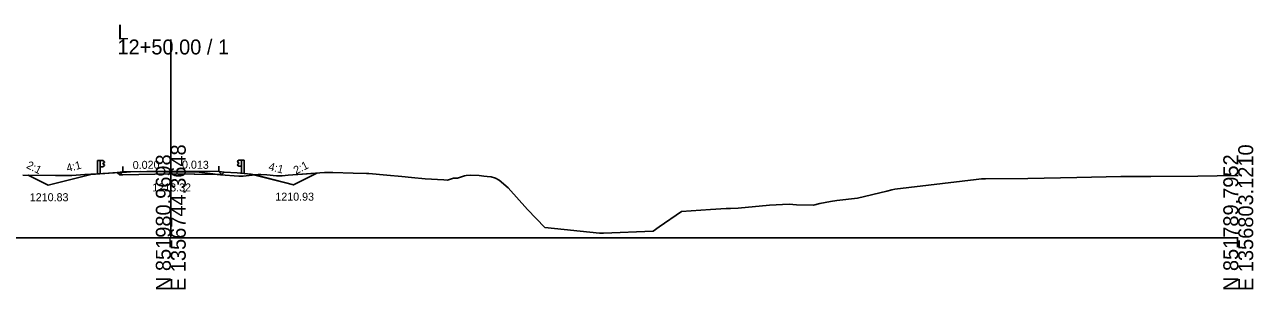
# Model space of a CAD drawing. Extents: x -26 to 3203, y -10 to 4066.
# Drawn here: x 172.6 to 402.8, y 1990.3 to 2039.9 of the extents above; entities that cross this region are included whole.
import ezdxf

# ---------------------------------------------------------------- set-up
doc = ezdxf.new("R2010")
doc.units = 0
for name, color, linetype in [('Exist Cross Section Cell', 7, 'Continuous'), ('Exist XS Center Line Elevation Label', 7, 'Continuous'), ('Exist XS Ground Line', 7, 'Continuous'), ('Prop XS Ditch Slope Text', 7, 'Continuous'), ('Prop XS Ditch Standard Text', 7, 'Continuous'), ('Prop XS Dump Level', 7, 'Continuous'), ('Prop XS Earthwork Shape', 7, 'Continuous'), ('Prop XS EOT Tick Mark', 7, 'Continuous'), ('Prop XS Finish Grade', 7, 'Continuous'), ('Prop XS Finish Grade Earthwork', 7, 'Continuous'), ('Prop XS Finish Grade Pavement', 7, 'Continuous'), ('Prop XS Guardrail', 7, 'Continuous'), ('Prop XS Pvmt Edge Slope', 7, 'Continuous'), ('Prop XS SE Text', 7, 'Continuous'), ('Prop XS Side Slope Text', 7, 'Continuous'), ('Prop XS Subgrade Earthwork', 7, 'Continuous')]:
    doc.layers.add(name, color=color, linetype=linetype)

msp = doc.modelspace()

# ---------------------------------------------------------------- linework, layer by layer
at = {"layer": 'Exist Cross Section Cell'}
for p, q in [((200, 2000), (200, 2037.13)), ((0, 2000), (200, 2000)), ((200, 2000), (400, 2000))]:
    msp.add_line(p, q, dxfattribs=at)
at = {"layer": 'Exist XS Ground Line'}
for p, q in [((183.89, 2011.81), (191.69, 2012.3)), ((191.69, 2012.3), (192.44, 2012.34)), ((192.44, 2012.34), (194.32, 2012.38)), ((194.32, 2012.38), (198.68, 2012.33)), ((198.68, 2012.33), (200, 2012.32)), ((200, 2012.32), (205.31, 2012.27)), ((205.31, 2012.27), (206.9, 2012.08)), ((172.29, 2011.71), (178.41, 2011.64)), ((178.41, 2011.64), (181.45, 2011.63)), ((181.45, 2011.63), (183.89, 2011.81)), ((206.9, 2012.08), (209.33, 2011.75)), ((209.33, 2011.75), (212.72, 2011.54)), ((212.72, 2011.54), (213.53, 2011.51)), ((213.53, 2011.51), (216.37, 2011.82)), ((216.37, 2011.82), (216.87, 2011.86)), ((216.87, 2011.86), (217.97, 2011.75)), ((217.97, 2011.75), (219.82, 2011.56)), ((219.82, 2011.56), (220.52, 2011.59)), ((220.52, 2011.59), (220.86, 2011.61)), ((220.86, 2011.61), (222, 2011.71)), ((222, 2011.71), (228.8, 2012.22)), ((228.8, 2012.22), (229.11, 2012.21)), ((229.11, 2012.21), (229.42, 2012.22)), ((229.42, 2012.22), (229.77, 2012.22)), ((229.77, 2012.22), (230.38, 2012.23)), ((230.38, 2012.23), (234.17, 2012.09)), ((234.17, 2012.09), (236.66, 2012.01)), ((236.66, 2012.01), (237.09, 2012.01)), ((237.09, 2012.01), (240.47, 2011.73)), ((240.47, 2011.73), (243.27, 2011.49)), ((243.27, 2011.49), (245.1, 2011.3)), ((245.1, 2011.3), (247.68, 2011.04)), ((247.68, 2011.04), (251.16, 2010.85)), ((251.16, 2010.85), (251.82, 2010.79)), ((251.82, 2010.79), (252.95, 2011.14)), ((252.95, 2011.14), (253.69, 2011.18)), ((253.69, 2011.18), (255, 2011.6)), ((255, 2011.6), (255.35, 2011.62)), ((255.35, 2011.62), (256.22, 2011.69)), ((256.22, 2011.69), (257.76, 2011.65)), ((257.76, 2011.65), (258.64, 2011.53)), ((258.64, 2011.53), (259.3, 2011.45)), ((259.3, 2011.45), (260.04, 2011.4)), ((260.04, 2011.4), (260.81, 2011.17)), ((260.81, 2011.17), (261.54, 2010.79)), ((261.54, 2010.79), (263.23, 2009.37)), ((335.67, 2009.1), (350.88, 2010.9)), ((350.88, 2010.9), (351.89, 2011)), ((351.89, 2011), (352.63, 2011)), ((352.63, 2011), (360.6, 2011.09)), ((360.6, 2011.09), (369.76, 2011.29)), ((369.76, 2011.29), (378.02, 2011.45)), ((378.02, 2011.45), (383.64, 2011.46)), ((383.64, 2011.46), (392.42, 2011.55)), ((392.42, 2011.55), (396.05, 2011.59)), ((396.05, 2011.59), (400, 2011.62)), ((263.23, 2009.37), (266.83, 2005.27)), ((328.67, 2007.38), (334.13, 2008.73)), ((334.13, 2008.73), (335.1, 2008.96)), ((335.1, 2008.96), (335.67, 2009.1)), ((301.11, 2005.25), (304.05, 2005.44)), ((304.05, 2005.44), (304.84, 2005.49)), ((304.84, 2005.49), (306.3, 2005.55)), ((306.3, 2005.55), (312.17, 2006.07)), ((312.17, 2006.07), (315.88, 2006.28)), ((315.88, 2006.28), (317.26, 2006.18)), ((317.26, 2006.18), (320.39, 2006.1)), ((320.39, 2006.1), (321.58, 2006.38)), ((321.58, 2006.38), (323.61, 2006.77)), ((323.61, 2006.77), (324.81, 2006.97)), ((324.81, 2006.97), (328.67, 2007.38)), ((266.83, 2005.27), (270.08, 2001.88)), ((291.47, 2002.02), (295.66, 2004.92)), ((295.66, 2004.92), (301.11, 2005.25)), ((270.08, 2001.88), (280.34, 2000.87)), ((280.34, 2000.87), (280.72, 2000.82)), ((280.72, 2000.82), (281.1, 2000.84)), ((281.1, 2000.84), (290.35, 2001.19)), ((290.35, 2001.19), (291.47, 2002.02))]:
    msp.add_line(p, q, dxfattribs=at)
at = {"layer": 'Prop XS Dump Level'}
for p, q in [((191, 2012.31), (200, 2012.49)), ((200, 2012.49), (209, 2012.37))]:
    msp.add_line(p, q, dxfattribs=at)
at = {"layer": 'Prop XS Earthwork Shape'}
for points in [[(190.45, 2011.76), (190.01, 2012.19), (191.69, 2012.3), (192.44, 2012.34), (194.32, 2012.38), (198.68, 2012.33), (200, 2012.32), (205.31, 2012.27), (206.9, 2012.08), (208.69, 2011.83), (200, 2011.95), (191, 2011.77)], [(209.55, 2011.82), (210.02, 2012.3), (212.42, 2012.12), (215, 2011.93), (215.74, 2011.75), (213.53, 2011.51), (212.72, 2011.54), (209.33, 2011.75), (208.69, 2011.83), (209, 2011.83)], [(187.62, 2012.04), (187.58, 2012.04), (185, 2011.83), (177, 2009.83), (173.27, 2011.7), (178.41, 2011.64), (181.45, 2011.63), (183.89, 2011.81)], [(190.01, 2012.19), (189.98, 2012.23), (187.62, 2012.04)], [(223, 2009.93), (227.35, 2012.11), (222, 2011.71), (220.86, 2011.61), (220.52, 2011.59), (219.82, 2011.56), (217.97, 2011.75), (216.87, 2011.86), (216.37, 2011.82), (215.74, 2011.75)]]:
    msp.add_lwpolyline(points, close=True, dxfattribs=at)
at = {"layer": 'Prop XS EOT Tick Mark'}
for p, q in [((191, 2012.31), (191, 2013.31)), ((209, 2012.37), (209, 2013.37))]:
    msp.add_line(p, q, dxfattribs=at)
at = {"layer": 'Prop XS Finish Grade'}
for p, q in [((191, 2012.31), (189.98, 2012.23)), ((209, 2012.37), (210.02, 2012.3))]:
    msp.add_line(p, q, dxfattribs=at)
at = {"layer": 'Prop XS Finish Grade Earthwork'}
for p, q in [((210.02, 2012.3), (212.42, 2012.12)), ((177, 2009.83), (173.27, 2011.7)), ((185, 2011.83), (177, 2009.83)), ((187.58, 2012.04), (185, 2011.83)), ((189.98, 2012.23), (187.58, 2012.04)), ((212.42, 2012.12), (215, 2011.93)), ((215, 2011.93), (223, 2009.93)), ((223, 2009.93), (227.35, 2012.11))]:
    msp.add_line(p, q, dxfattribs=at)
at = {"layer": 'Prop XS Finish Grade Pavement'}
for p, q in [((191, 2012.31), (200, 2012.49)), ((200, 2012.49), (209, 2012.37))]:
    msp.add_line(p, q, dxfattribs=at)
at = {"layer": 'Prop XS Guardrail'}
for p, q in [((186.26, 2014.43), (186.76, 2014.43)), ((186.26, 2011.93), (186.26, 2014.43)), ((186.76, 2014.43), (187.26, 2014.43)), ((186.76, 2014.43), (186.76, 2011.93)), ((187.26, 2013.3), (186.76, 2013.3)), ((187.26, 2014.43), (187.55, 2014.23)), ((187.55, 2014.11), (187.26, 2013.91)), ((187.26, 2013.91), (187.26, 2013.82)), ((187.26, 2013.82), (187.55, 2013.62)), ((187.55, 2013.5), (187.26, 2013.3)), ((187.55, 2014.23), (187.58, 2014.17)), ((187.58, 2014.17), (187.55, 2014.11)), ((187.55, 2013.62), (187.58, 2013.56)), ((187.58, 2013.56), (187.55, 2013.5)), ((212.47, 2014.32), (212.44, 2014.26)), ((212.44, 2014.26), (212.47, 2014.2)), ((212.47, 2013.71), (212.44, 2013.65)), ((212.44, 2013.65), (212.47, 2013.59)), ((212.76, 2014.52), (212.47, 2014.32)), ((212.47, 2014.2), (212.76, 2014)), ((212.76, 2013.91), (212.47, 2013.71)), ((212.47, 2013.59), (212.76, 2013.39)), ((213.26, 2014.52), (212.76, 2014.52)), ((212.76, 2014), (212.76, 2013.91)), ((212.76, 2013.39), (213.26, 2013.39)), ((213.76, 2014.52), (213.26, 2014.52)), ((213.26, 2014.52), (213.26, 2012.02)), ((213.76, 2012.02), (213.76, 2014.52))]:
    msp.add_line(p, q, dxfattribs=at)
at = {"layer": 'Prop XS Pvmt Edge Slope'}
for p, q in [((191, 2012.31), (190.45, 2011.76)), ((209, 2012.37), (209.55, 2011.82))]:
    msp.add_line(p, q, dxfattribs=at)
at = {"layer": 'Prop XS Subgrade Earthwork'}
for p, q in [((209.55, 2011.82), (210.02, 2012.3)), ((190.45, 2011.76), (189.98, 2012.23)), ((191, 2011.77), (190.45, 2011.76)), ((200, 2011.95), (191, 2011.77)), ((209, 2011.83), (200, 2011.95)), ((209, 2011.83), (209.55, 2011.82))]:
    msp.add_line(p, q, dxfattribs=at)

# ---------------------------------------------------------------- texts
at = {"layer": 'Exist Cross Section Cell'}
for s, p in [('L', (190, 2037.13)), ('12+50.00 / 1', (190, 2034.33))]:
    msp.add_text(s, height=2.8, dxfattribs=at).set_placement(p)
for s, p in [('E 1356744.3648', (202.8, 1990)), ('E 1356803.1210', (402.8, 1990)), ('N 851980.9698', (200, 1990)), ('N 851789.7952', (400, 1990))]:
    msp.add_text(s, height=2.8, rotation=90, dxfattribs=at).set_placement(p)
at = {"layer": 'Exist XS Center Line Elevation Label'}
msp.add_text('1213.32', height=1.5, dxfattribs=at).set_placement((196.54, 2008.66))
at = {"layer": 'Prop XS Ditch Slope Text'}
for rotation, p in [(14.0362, (180.64, 2012.29)), (345.9638, (218.21, 2012.68))]:
    msp.add_text('4:1', height=1.5, rotation=rotation, dxfattribs=at).set_placement(p)
at = {"layer": 'Prop XS Ditch Standard Text'}
for s, p in [('1210.83', (173.58, 2006.83)), ('1210.93', (219.58, 2006.93))]:
    msp.add_text(s, height=1.5, dxfattribs=at).set_placement(p)
at = {"layer": 'Prop XS Dump Level'}
for p in [(187.58, 2012), (212.42, 2012.08)]:
    msp.add_text('Case1', height=0.04, dxfattribs=at).set_placement(p)
at = {"layer": 'Prop XS SE Text'}
for s, rotation, p in [('0.020', 1.1458, (192.88, 2012.85)), ('0.013', 359.2361, (202.09, 2012.96))]:
    msp.add_text(s, height=1.5, rotation=rotation, dxfattribs=at).set_placement(p)
at = {"layer": 'Prop XS Side Slope Text'}
for rotation, p in [(333.4349, (172.83, 2013.11)), (26.5651, (223.45, 2011.83))]:
    msp.add_text('2:1', height=1.5, rotation=rotation, dxfattribs=at).set_placement(p)

doc.saveas('drawing.dxf')
